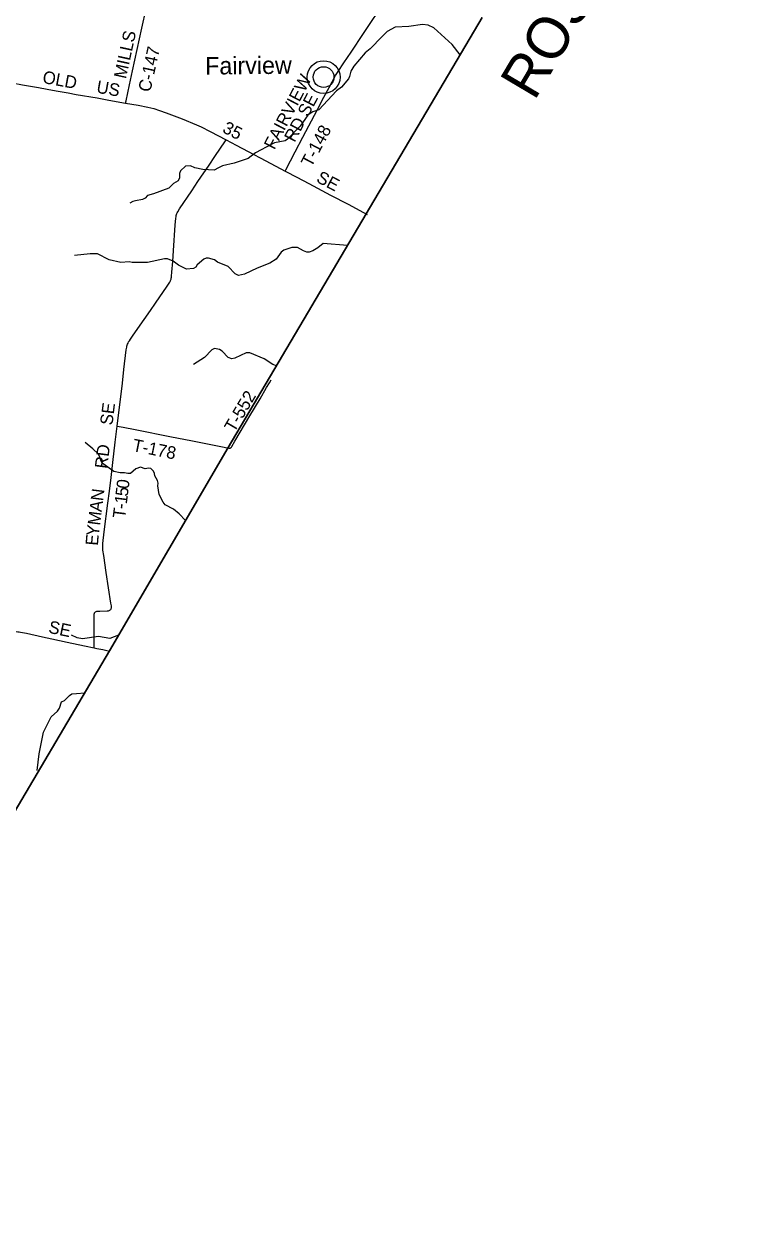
# Model space of a CAD drawing. Extents: x -51392 to 1635000, y 156707 to 696232.
# Drawn here: x 169473 to 186512, y 438581 to 467379 of the extents above; entities that cross this region are included whole.
import ezdxf

# ---------------------------------------------------------------- set-up
doc = ezdxf.new("R2010")
doc.units = 0
for name, color, linetype in [('GM_X_Adjacent_County', 7, 'Continuous'), ('GM_X_Adjacent_County_Text', 7, 'Continuous'), ('GM_X_County', 7, 'Continuous'), ('GM_X_County_Road', 7, 'Continuous'), ('GM_X_County_Road_Text', 7, 'Continuous'), ('GM_X_Minor_River', 7, 'Continuous'), ('GM_X_Township', 7, 'Continuous'), ('GM_X_Township_Road', 7, 'Continuous'), ('GM_X_Township_Road_Text', 7, 'Continuous'), ('GM_X_Unincorporated', 7, 'Continuous'), ('GM_X_Unincorporated_Text', 7, 'Continuous')]:
    doc.layers.add(name, color=color, linetype=linetype)

msp = doc.modelspace()

# ---------------------------------------------------------------- linework, layer by layer
at = {"layer": 'GM_X_Adjacent_County'}
msp.add_lwpolyline([(163108, 438102), (165204, 441649), (168165, 446678), (168653, 447506), (168679, 447550), (171521, 452359), (174363, 457229), (177674, 462830), (180454, 467533)], dxfattribs=at)
at = {"layer": 'GM_X_County'}
msp.add_lwpolyline([(180454, 467533), (177674, 462830), (174363, 457229), (171521, 452359), (168679, 447550), (168653, 447506), (168165, 446678), (165204, 441649), (163108, 438102), (160967, 434456), (157733, 428962), (157643, 428810), (156964, 428817), (155079, 428826), (152105, 428841)], dxfattribs=at)
at = {"layer": 'GM_X_County_Road'}
for points in [[(171907, 465486), (171918, 465535), (172003, 465919), (172076, 466256), (172188, 466769), (172300, 467282), (172501, 468212), (172582, 468580), (172615, 468741), (172666, 468965), (172731, 469253), (172809, 469605), (172839, 469733), (172853, 469780), (172873, 469825), (172892, 469855)], [(167635, 466242), (167785, 466212), (167931, 466187), (168141, 466152), (168480, 466091), (168706, 466051), (168916, 466015), (169191, 465968), (169434, 465926), (169821, 465857), (170031, 465820), (170241, 465782), (170532, 465731), (170725, 465694), (171227, 465609), (171469, 465566), (171856, 465494), (171907, 465486)], [(171907, 465486), (172212, 465433), (172437, 465388), (172581, 465353), (172722, 465309), (172877, 465254), (173260, 465107), (173610, 464966), (173715, 464919), (173934, 464807), (174315, 464606)], [(174315, 464606), (174558, 464478), (174848, 464323), (175268, 464101), (175731, 463856)], [(175731, 463856), (175747, 463848), (176009, 463712), (176299, 463558), (176820, 463281), (177241, 463060), (177701, 462818)], [(167885, 452642), (167904, 452635), (167929, 452628), (167954, 452624), (167976, 452622), (167997, 452622), (168025, 452624), (168106, 452634), (168494, 452699), (168784, 452751), (168978, 452785), (169158, 452813), (169209, 452818), (169255, 452822), (169286, 452821), (169322, 452819), (169356, 452815), (169387, 452811), (169531, 452781), (169916, 452698), (170141, 452650), (170509, 452570), (170926, 452481), (171155, 452432)], [(171155, 452432), (171215, 452419), (171359, 452390), (171520, 452353)]]:
    msp.add_lwpolyline(points, dxfattribs=at)
at = {"layer": 'GM_X_Minor_River'}
for points in [[(179926, 466637), (179731, 466887), (179297, 467289), (179162, 467355), (179022, 467370), (178698, 467323), (178370, 467304), (178179, 467201), (178057, 467084), (177766, 466786), (177651, 466690), (177374, 466372), (177304, 466247), (177271, 466125), (177251, 466068), (177084, 465869), (176960, 465780), (176538, 465322), (176392, 465275), (176276, 465196), (176217, 465116), (176093, 464935), (175791, 464619), (175729, 464583), (175473, 464530), (175409, 464499), (175024, 464295), (174846, 464154), (174510, 464047), (174231, 463982), (174131, 463931), (174027, 463875), (173757, 463892), (173570, 463934), (173460, 463983), (173340, 463971), (173227, 463862), (173201, 463796), (173197, 463694), (173168, 463623), (173056, 463555), (172944, 463444), (172573, 463312), (172433, 463270), (172377, 463210), (172309, 463171), (172143, 463143), (172079, 463124), (172007, 463084)], [(177228, 462076), (176641, 462119), (176516, 462015), (176396, 461944), (176306, 461916), (176250, 461916), (176174, 461941), (176027, 462023), (175891, 462025), (175697, 461964), (175638, 461910), (175516, 461743), (175361, 461650), (175063, 461529), (174756, 461385), (174616, 461351), (174531, 461396), (174369, 461568), (174110, 461674), (174040, 461728), (173892, 461770), (173842, 461769), (173786, 461747), (173624, 461612), (173592, 461554), (173532, 461524), (173368, 461507), (173172, 461603), (173044, 461701), (172911, 461756), (172841, 461756), (172435, 461665), (172251, 461664), (172191, 461668), (172065, 461663), (171995, 461681), (171797, 461667), (171517, 461726), (171236, 461872), (171060, 461873), (170686, 461834)], [(175522, 459188), (175439, 459220), (175232, 459358), (174883, 459497), (174795, 459503), (174526, 459372), (174450, 459357), (174366, 459391), (174221, 459541), (174155, 459583), (174035, 459603), (173971, 459573), (173795, 459388), (173534, 459220)], [(173344, 455482), (173191, 455643), (173052, 455755), (172856, 455857), (172808, 455919), (172713, 456107), (172682, 456316), (172690, 456374), (172671, 456442), (172605, 456556), (172603, 456607), (172576, 456663), (172516, 456727), (172454, 456739), (172380, 456718), (172264, 456758), (172152, 456718), (172026, 456613), (171958, 456611), (171884, 456628), (171774, 456624), (171628, 456658), (171371, 456841), (171319, 456903), (171284, 457026), (171250, 457082), (171124, 457198), (170939, 457356)], [(171740, 452734), (171529, 452658), (171254, 452703), (170875, 452646), (170750, 452670), (170612, 452739)], [(169791, 449490), (169832, 449891), (169938, 450411), (170122, 450781), (170274, 450918), (170325, 450989), (170373, 451135), (170441, 451172), (170562, 451288), (170622, 451331), (170730, 451341), (170929, 451354)]]:
    msp.add_lwpolyline(points, dxfattribs=at)
at = {"layer": 'GM_X_Township'}
msp.add_lwpolyline([(180454, 467533), (177674, 462830), (174363, 457229), (171521, 452359), (168679, 447550), (168653, 447506), (168165, 446678), (165204, 441649), (163108, 438102)], dxfattribs=at)
at = {"layer": 'GM_X_Township_Road'}
for points in [[(175731, 463856), (175745, 463882), (175974, 464317), (176158, 464665), (176510, 465333), (176662, 465623), (176786, 465855), (176940, 466144), (177000, 466242), (177136, 466447), (177310, 466706), (177613, 467154), (177849, 467509), (177903, 467589)], [(171707, 457741), (171832, 458775), (171869, 459101), (171924, 459574), (171934, 459639), (171940, 459661), (171947, 459687), (171954, 459707), (171966, 459733), (171980, 459762), (171998, 459791), (172021, 459825), (172092, 459926), (172354, 460302), (172503, 460519), (172624, 460694), (172903, 461099), (172967, 461195), (172981, 461224), (172986, 461235), (172991, 461248), (172997, 461269), (173002, 461292), (173005, 461313), (173008, 461338), (173016, 461431), (173036, 461693), (173055, 461954), (173099, 462560), (173111, 462724), (173116, 462759), (173122, 462789), (173128, 462812), (173136, 462837), (173145, 462859), (173157, 462882), (173202, 462951), (173496, 463386), (173642, 463604), (173907, 463999), (174045, 464203), (174300, 464584), (174315, 464606)], [(174391, 457215), (174395, 457215), (174397, 457215), (174401, 457215), (174407, 457216), (174413, 457218), (174420, 457221), (174428, 457227), (174437, 457234), (174445, 457244), (174452, 457256), (174528, 457387), (174887, 457993), (175129, 458401), (175287, 458670), (175355, 458782), (175399, 458851)], [(171155, 452432), (171155, 452483), (171156, 452712), (171155, 452859), (171154, 452990), (171152, 453204), (171153, 453224), (171155, 453238), (171157, 453247), (171161, 453259), (171165, 453270), (171176, 453284), (171182, 453289), (171189, 453295), (171204, 453303), (171220, 453308), (171237, 453312), (171254, 453313), (171290, 453314), (171467, 453317), (171488, 453319), (171501, 453321), (171514, 453326), (171529, 453332), (171541, 453340), (171552, 453351), (171560, 453364), (171565, 453378), (171568, 453393), (171569, 453407), (171568, 453420), (171566, 453438), (171557, 453506), (171445, 454235), (171384, 454641), (171364, 454771), (171359, 454853), (171359, 454887), (171362, 454935), (171396, 455212), (171481, 455896), (171518, 456189), (171558, 456514), (171602, 456872), (171660, 457360), (171707, 457741)], [(171707, 457741), (171846, 457718), (172135, 457661), (173004, 457489), (173470, 457398), (173711, 457349), (174193, 457254), (174381, 457216), (174387, 457215), (174391, 457215)]]:
    msp.add_lwpolyline(points, dxfattribs=at)
at = {"layer": 'GM_X_Unincorporated'}
for radius in [393, 249]:
    msp.add_circle((176653, 466108), radius, dxfattribs=at)

# ---------------------------------------------------------------- texts
at = {"layer": 'GM_X_Adjacent_County_Text'}
msp.add_text('ROSS COUNTY', height=1000, rotation=59.3193, dxfattribs=at).set_placement((181704, 465519))
at = {"layer": 'GM_X_County_Road_Text'}
for s, rotation, p in [('MILLS', 77.6641, (171915, 466052)), ('C-147', 77.5636, (172498, 465733)), ('OLD', 349.5523, (169900, 465970)), ('US', 349.8522, (171194, 465736)), ('35', 332.7501, (174207, 464797)), ('SE', 332.3958, (176456, 463609)), ('SE', 348.0771, (170041, 452796))]:
    msp.add_text(s, height=300, rotation=rotation, dxfattribs=at).set_placement(p)
at = {"layer": 'GM_X_Township_Road_Text'}
for s, rotation, p in [('FAIRVIEW', 62.3508, (175472, 464350)), ('RD SE', 62.123, (175957, 464527)), ('T-148', 62.2182, (176360, 463929)), ('T-552', 59.3099, (174512, 457577)), ('SE', 82.9049, (171591, 457755)), ('T-178', 348.6789, (172055, 457150)), ('RD', 82.7955, (171464, 456714)), ('0', 83.0082, (171981, 456231)), ('N', 82.9313, (171366, 455940)), ('5', 83.0009, (171958, 456049)), ('A', 82.9282, (171334, 455678)), ('1', 82.9768, (171936, 455867)), ('-', 82.959, (171921, 455746)), ('M', 82.9314, (171294, 455355)), ('T', 82.9085, (171893, 455523)), ('Y', 82.987, (171261, 455093)), ('E', 85.0962, (171243, 454873))]:
    msp.add_text(s, height=300, rotation=rotation, dxfattribs=at).set_placement(p)
at = {"layer": 'GM_X_Unincorporated_Text'}
msp.add_text('Fairview', height=417, rotation=0.5386, dxfattribs=at).set_placement((173816, 466168))

doc.saveas('drawing.dxf')
